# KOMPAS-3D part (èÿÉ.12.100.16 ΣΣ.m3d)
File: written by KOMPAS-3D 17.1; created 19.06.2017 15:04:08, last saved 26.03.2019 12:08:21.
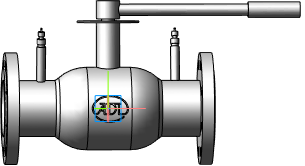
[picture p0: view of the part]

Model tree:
1. Операция без истории:2  (labels: Сталь 20  ГОСТ 1050-88)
